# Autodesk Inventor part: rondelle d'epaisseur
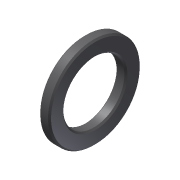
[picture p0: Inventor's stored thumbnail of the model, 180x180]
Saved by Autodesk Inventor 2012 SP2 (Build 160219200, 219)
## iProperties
Created: 2013-04
Part Number: rondelle d'epaisseur
Material: Default
Document SubType Name: Modeling
Designer: papa
Density: 1 g/cm^3
Mass: 0.288398 g
Surface Area: 4.47538 cm^2
Volume: 0.288398 cm^3
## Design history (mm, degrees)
node "rondelle d'epaisseur1"
node "rondelle d'epaisseur"
node "Base1"
